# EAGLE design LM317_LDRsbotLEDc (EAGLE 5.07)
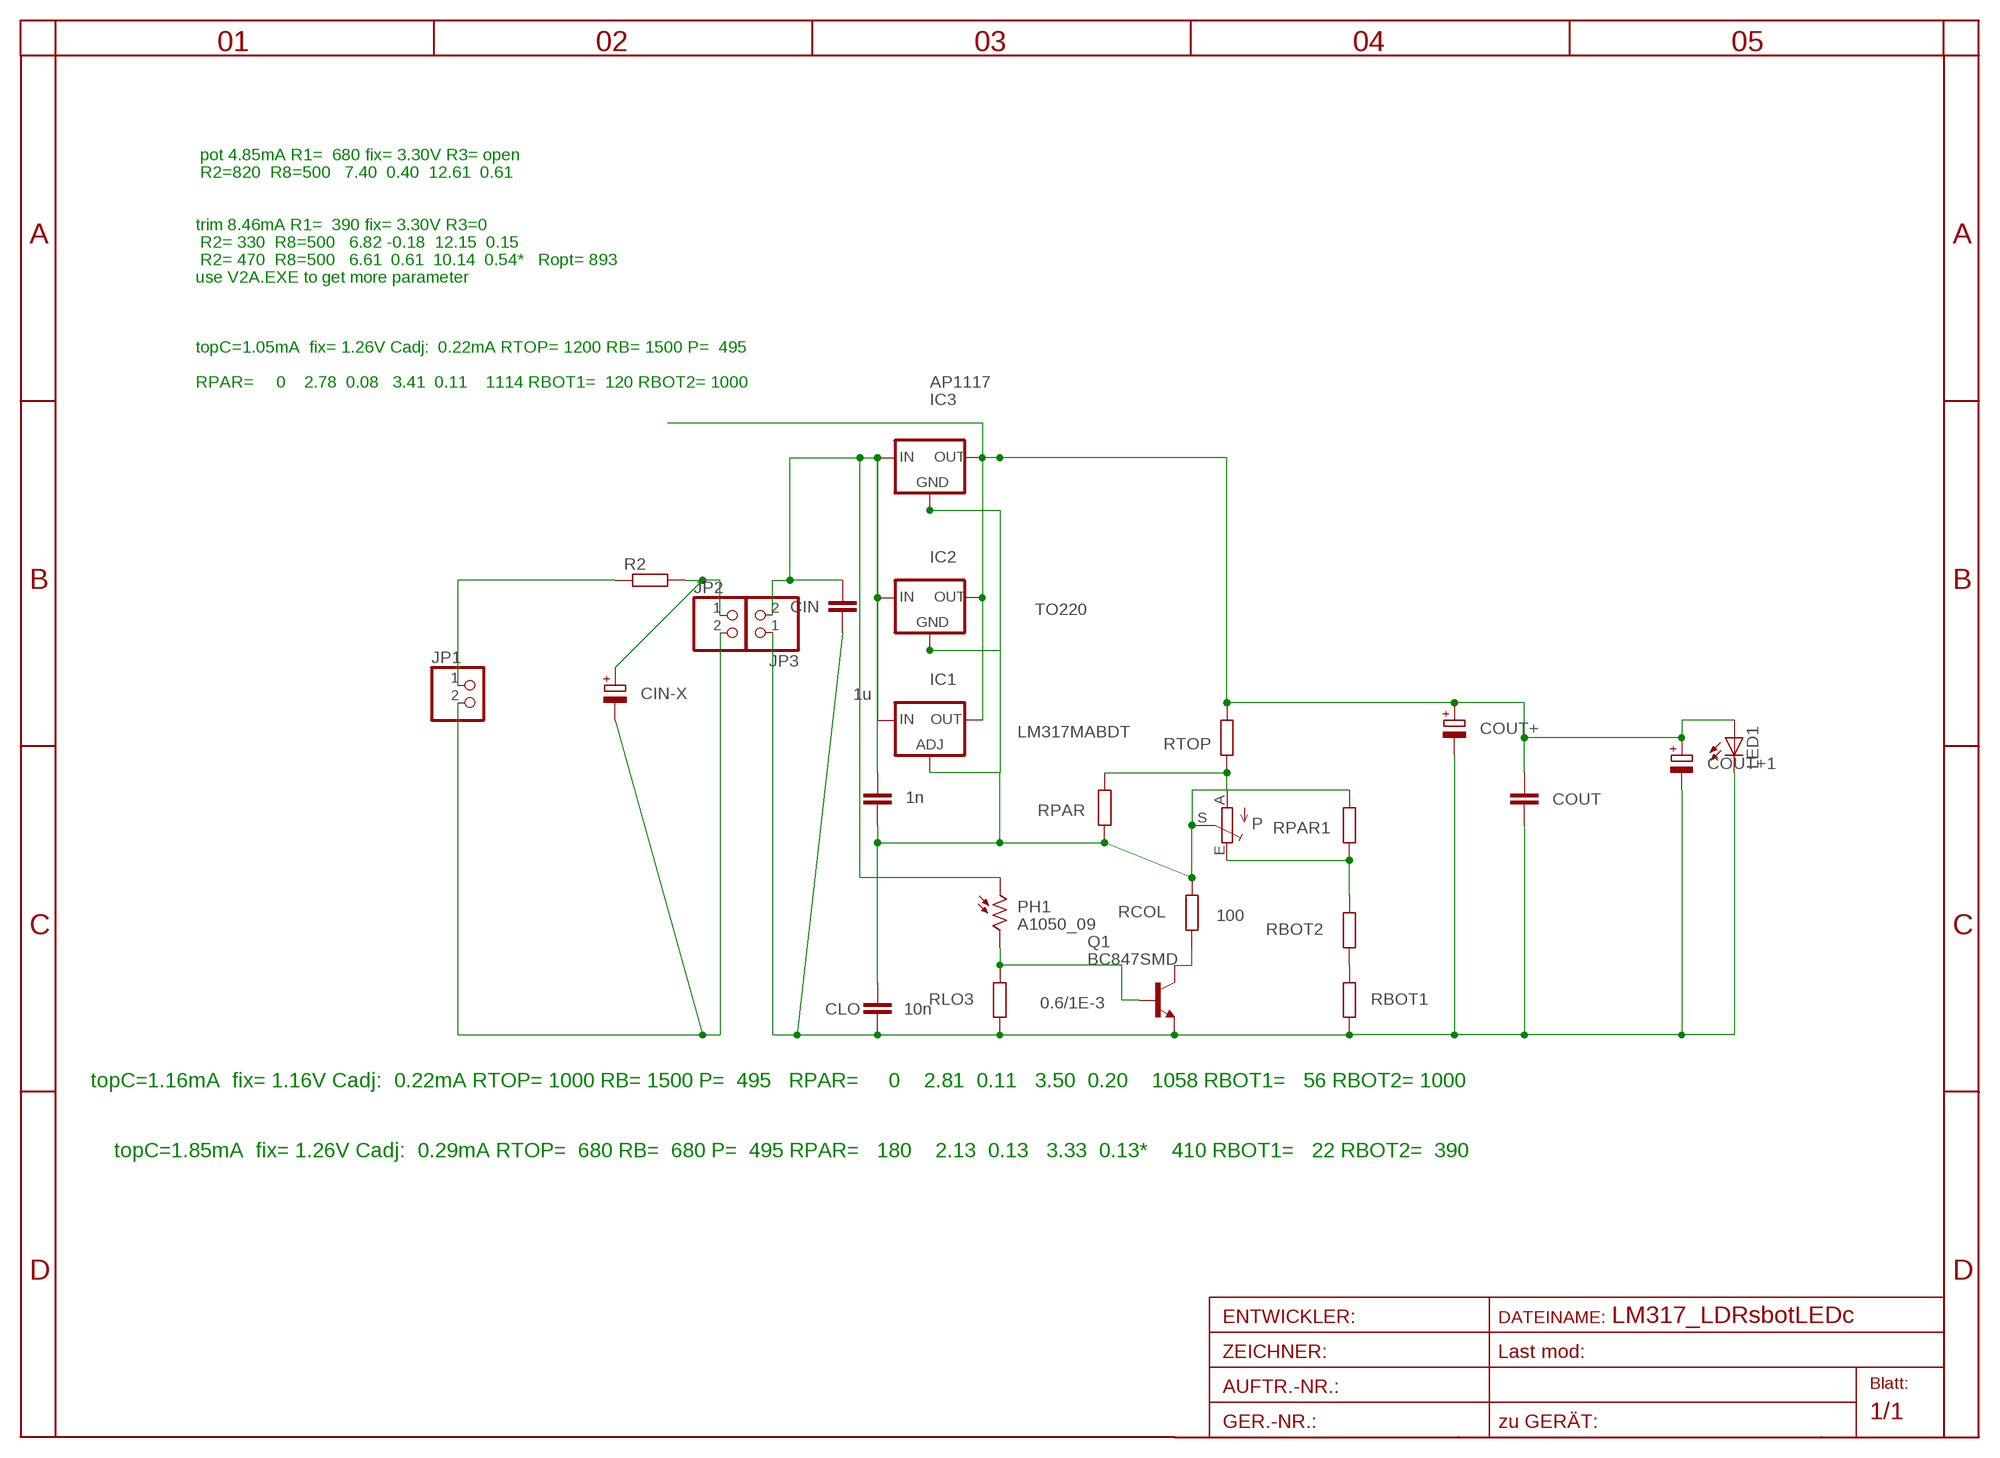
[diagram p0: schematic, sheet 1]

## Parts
CHI  1n  C-EUC0805  [C0805]
CIN  1u  C-EUC1206  [C1206]
CIN-X  CPOL-EUE3.5-8  [E3,5-8]
CLO  10n  C-EUC0805  [C0805]
COUT  C-EUC1206  [C1206]
COUT+  CPOL-EUE7.5-16  [E7,5-16]
COUT+1  CPOL-EUE7.5-16  [E7,5-16]
IC1  LM317MABDT  [DPACK]
IC2  TO220  78XXS  [78XXS]
IC3  AP1117  [SOT223]
JP1  PINHD-1X2STR  [1X02]
JP2  PINHD-1X2STR  [1X02]
JP3  PINHD-1X2STR  [1X02]
LED1  LED1W1MM6  [1W1MM6]
P  TRIM_EU-RAND160  [RANDL]
PH1  A1050_09  [T0-46-A10XX]
Q1  BC847SMD  [SOT23]
R2  R-EU_R1210  [R1210]
RBOT1  R-EU_R0805  [R0805]
RBOT2  R-EU_R0805  [R0805]
RCOL  100  R-EU_R0805  [R0805]
RLO3  0.6/1E-3  R-EU_R0805  [R0805]
RPAR  R-EU_R0805  [R0805]
RPAR1  R-EU_R0805  [R0805]
RTOP  R-EU_R0805  [R0805]

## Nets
GND: CIN.2 CLO.2 COUT+1.- COUT+.- COUT.2 JP3.1 LED1.C Q1.2(E) RBOT1.1 RLO3.1
IN: CHI.1 CIN.1 IC1.3(IN) IC2.IN IC3.3(IN) JP3.2 PH1.1
N$1: P.E RBOT2.2 RPAR1.1
N$2: RBOT1.2 RBOT2.1
N$3: Q1.3(C) RCOL.1
N$4: CHI.2 CLO.1 IC1.1(ADJ) IC2.GND IC3.1(GND) P.S RCOL.2 RPAR1.2 RPAR.1
N$5: PH1.2 Q1.1(B) RLO3.2
N$6: JP1.1 R2.1
N$7: P.A RPAR.2 RTOP.1
OUT: COUT+1.+ COUT+.+ COUT.1 IC1.4(OUT) IC2.OUT IC3.2(OUT) IC3.4(TAB) LED1.A RTOP.2
VINX: CIN-X.- JP1.2 JP2.2
VPROT: CIN-X.+ JP2.1 R2.2

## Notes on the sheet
- pot 4.85mA R1=  680 fix= 3.30V R3= open
- R2=820  R8=500   7.40  0.40  12.61  0.61
- trim 8.46mA R1=  390 fix= 3.30V R3=0
- R2= 330  R8=500   6.82 -0.18  12.15  0.15
- R2= 470  R8=500   6.61  0.61  10.14  0.54*   Ropt= 893
- use V2A.EXE to get more parameter
- topC=1.05mA  fix= 1.26V Cadj:  0.22mA RTOP= 1200 RB= 1500 P=  495
- RPAR=     0    2.78  0.08   3.41  0.11    1114 RBOT1=  120 RBOT2= 1000
- topC=1.16mA  fix= 1.16V Cadj:  0.22mA RTOP= 1000 RB= 1500 P=  495   RPAR=     0    2.81  0.11   3.50  0.20    1058 RBOT1=   56 RBOT2= 1000
- topC=1.85mA  fix= 1.26V Cadj:  0.29mA RTOP=  680 RB=  680 P=  495 RPAR=   180    2.13  0.13   3.33  0.13*    410 RBOT1=   22 RBOT2=  390

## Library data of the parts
CHI CIN CLO COUT = rcl:C-EU: CAPACITOR, European symbol
CIN-X COUT+ COUT+1 = rcl:CPOL-EU: POLARIZED CAPACITOR, European symbol
IC1 = v-reg:LM317?*: 500 mA Adjustable Output Positive Voltage Regulator Source: http://www.onsemi.co.jp .. LM317M-D.PDF
IC2 = v-reg:78XXS: VOLTAGE REGULATOR
IC3 = v-reg:AP1117
JP1-JP3 = pinhead:PINHD-1X2: PIN HEADER
LED1 = led:LED: LED
P = pot:TRIM_EU-: POTENTIOMETER
PH1 = photo-elements:A10: Sensor Robust Light Sensing Applications
Q1 = transistor-npn:BC847*: NPN Transistor
R2 RBOT1 RBOT2 RCOL RLO3 RPAR RPAR1 RTOP = rcl:R-EU_: RESISTOR, European symbol

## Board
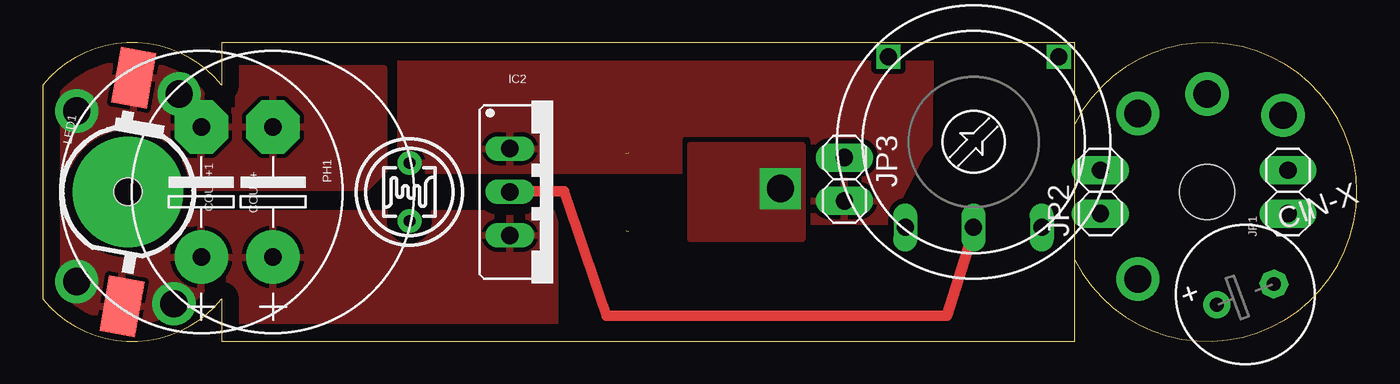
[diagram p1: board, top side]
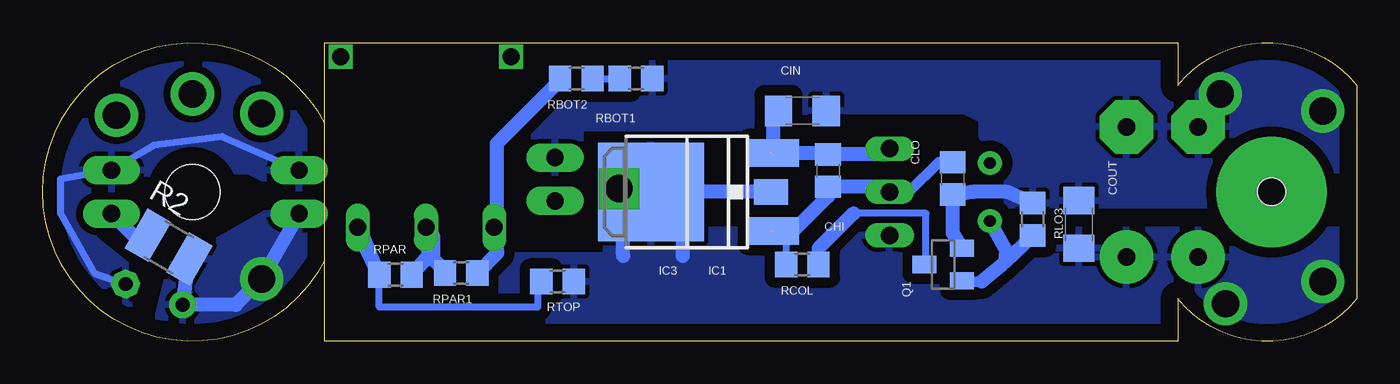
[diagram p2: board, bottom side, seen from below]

Size 77.03 x 17.5 mm. Coordinates in mm from the lower left corner, seen from the top.
Outline: 60.5,4.75 60.5,0 10.5,0 10.5,2.5 arc-102 0,2.5 0,15 arc-102 10.5,15 10.5,17.5 60.5,17.5 60.5,12.75
Outline: 60.5,4.75 60.5,12.75
Outline: 60.5,4.75 arc306 60.5,12.75
Copper layers (1*16): Top 0.035mm / dielectric 1.5mm / Bottom 0.035mm
Design rules "default *": minimum track width 10mil, minimum drill 20mil, track to track 8mil, track to pad 8mil, pad to pad 8mil, via to via 8mil, smd to smd 8mil, copper to edge 40mil, drill to drill 8mil, minimum pad ring 8mil, minimum via ring 8mil, stop-mask expansion 8mil, vias tented up to drill 0mil, thermal gap 10mil
Holes 3.2 mm at 68.25,8.75

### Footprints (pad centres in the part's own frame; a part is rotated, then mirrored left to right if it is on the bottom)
C0805 = smd 1.3 x 1.5: 1 -0.95,0; 2 0.95,0
C1206 = smd 1.6 x 1.8: 1 -1.4,0; 2 1.4,0
E3,5-8 = drill 0.813 pad 1.6 round: + -1.778,0 | drill 0.813 pad 1.6 octagon: - 1.778,0
E7,5-16 = drill 1.016 pad 3.15 round: + -3.81,0 | drill 1.016 pad 3.15 octagon: - 3.81,0
DPACK = smd 1.6 x 3: 1 -2.28,-4.8; 3 2.28,-4.8 | smd 5.8 x 6.2: 4 0,2.38
78XXS = drill 1.016 long: GND 0,-2.54; IN -2.54,-2.54; OUT 2.54,-2.54
SOT223 = smd 1.5 x 2: 1 -2.3,-3.15; 2 0,-3.15; 3 2.3,-3.15 | smd 3.8 x 2: 4 0,3.15
1X02 = drill 1.016 pad 1.676 long: 1 -1.27,0; 2 1.27,0
1W1MM6 = smd 3.3 x 2.1: A -6.65,-0.82; C 6.65,0.82 | drill 1.6 pad 6.452 round: P$1 0,0 | hole 1.6: 0,0
RANDL = drill 1 long: A -4,5; E 4,5; S 0,5 | drill 1 square: P$1 -5,-5; P$2 5,-5
T0-46-A10XX = drill 0.7 pad 1.4 round: 1 -1.7,0; 2 1.7,0
SOT23 = smd 1 x 1.4: 1 -0.95,-1.1; 2 0.95,-1.1; 3 0,1.1
R1210 = smd 1.6 x 2.7: 1 -1.4,0; 2 1.4,0
R0805 = smd 1.3 x 1.5: 1 -0.95,0; 2 0.95,0

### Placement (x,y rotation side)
CHI  31,10 270 bottom
CIN  32.5,13.5 0 bottom
CIN-X  70.5,2.75 20 top
CLO  23.7,9.55 270 bottom
COUT  16.3,6.85 90 bottom
COUT+  13.5,8.75 90 top
COUT+1  9.3,8.75 90 top
IC1  39,8.75 90 bottom
IC2  29.93,8.75 270 top
IC3  37.5,8.75 90 bottom
JP1  73,8.75 90 top
JP2  62,8.75 90 top
JP3  47,9.5 270 top
LED1  5,8.75 80 top
P  54.57,11.68 180 top
PH1  21.5,8.75 270 top
Q1  24.25,4.5 90 bottom
R2  69.64,5.52 330 bottom
RBOT1  42.25,15.4 180 bottom
RBOT2  45.75,15.4 180 bottom
RCOL  32.5,4.5 180 bottom
RLO3  19,7.15 270 bottom
RPAR  56.35,3.9 180 bottom
RPAR1  52.5,4 180 bottom
RTOP  46.85,3.5 0 bottom

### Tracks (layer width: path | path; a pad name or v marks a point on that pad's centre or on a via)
GND  (via drill 1.6 pad 2.54)
  Bottom 0.813: RLO3.1 20.5,8.75 22.5,8.75 23.8,8.5 CLO.2 23.7,6.35 Q1.2
  other vias: 8,14.5 2,13.5
  pour Bottom (isolate 0.61): 0,15.5 arc-92 11,15 11,17.5 48.5,17 48.5,9.5 45.5,9.5 45.5,12.5 35,12.5 32.1,13.55 31,13.5 23,13.5 22,13 22,12 20.5,10.5 20.5,8 0,8
  pour Top (isolate 0.406, rank 3): 0.5,15 arc-78 10,15 10,13.5 11.5,13.5 11.5,16 20,16 20,10 19,9 9,9 6,12 3.5,12 0.5,9.5
IN  (1 unrouted)
  Bottom 0.813: CIN.1 34.2,13.5 IC1.3 31,11.03 CHI.1 27.73,10.95 IC2.IN
  pour Top (isolate 0.305, rank 2): 52,16.57 52,15.5 51.94,11.5 51.5,11 49.5,7 45,7 45,10 21,10 21,16.5
N$1
  Bottom 0.813: RBOT2.2 46.7,15.3 50.4,11.6 50.4,6.46 P.E 50.37,5.18 RPAR1.1
N$2
  Bottom 0.406: RBOT2.1 RBOT1.2
N$3
  Bottom 0.406: 29.5,7.5 25.25,7.5 25.25,4.9 Q1.3
  Bottom 0.813: RCOL.1 31.55,5.45 29.5,7.5
N$4  (1 unrouted)
  Top 0.406: IC2.GND 27.74,8.8
  Top 0.61: P.S 54.37,5.87 53,1.5 33.05,1.5 30.55,8.8 27.74,8.8
  Bottom 0.406: RCOL.2 33.45,5.72 IC1.1 | 26.25,8.75 IC2.GND | CLO.1 24.5,10.5
  Bottom 0.61: 24.5,10.5 26.25,8.75
  Bottom 0.813: RPAR.1 54.4,5.05 P.S 54.15,6.21 54.15,4.8 53.45,4.2 RPAR1.2 | IC2.GND 27.69,9.05 CHI.2 31,8.5 33,6.5 34.17,6.5 IC1.1
N$5
  Bottom 0.406: 20.6,4.66 20.85,4.45 | 23.1,3.5 Q1.1
  Bottom 0.61: 22,3.5 23.1,3.5
  Bottom 0.813: RLO3.2 20.6,4.66 20.55,5.31 PH1.2 | 20.85,4.45 22,3.5
N$6
  Bottom 0.813: R2.1 71.74,6.22 JP1.1
N$7
  Bottom 0.406: RTOP.1 48,3.5 48,2 57.3,2 RPAR.2
  Bottom 0.813: P.A 58.34,6.4 RPAR.2 58.2,5.72
N$14  (via drill 1.6 pad 2.54)
  other vias: 72.7,13.25
N$15  (via drill 1.6 pad 2.54)
  other vias: 68.25,14.5
N$16  (via drill 1.6 pad 2.54)
  other vias: 64.2,13.35
OUT  (via drill 1.6, 1.6 pad 2.54)
  Bottom 0.813: IC3.2 IC3.4 | 39.5,5 39.5,6.5 | 43,5 43,6.5
  other vias: 43.25,8.95 2,3.5 7.7,2.2
  pour Bottom (isolate 0.61, rank 2): 38,11.5 44,11.5 44,5 55,5 55,0.5 0.5,0.5 0.5,6.5 38,6.5
  pour Top (isolate 0.61): 29.5,0 10.5,0 10.5,1.5 arc-67 0,1.5 0,7.5 30,7.5 30,1
  pour Top (isolate 0.406): 38,11.5 44.5,11.5 44.5,6 38,6
VINX
  Bottom 0.406: JP2.2 66.5,12 70.5,11.5 JP1.2 76,9.5 76,7.5 74,4 CIN-X.-
  pour Bottom (isolate 0.406): 61,12 63.5,16.5 73,16 76.5,10 76.5,7 74,2 72,2 71.5,4 74,6 74.5,8 70.5,10 65,10 63,9 60.5,9
VPROT  (via drill 1.6 pad 2.54)
  Bottom 0.813: JP2.1 v64.2,3.65 65.71,2.14 CIN-X.+ R2.2
  pour Bottom (isolate 0.406): 61,8 61,5 63,2 67,0.5 70.5,0.5 69.5,4.5 67.5,5.5 64,7.5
